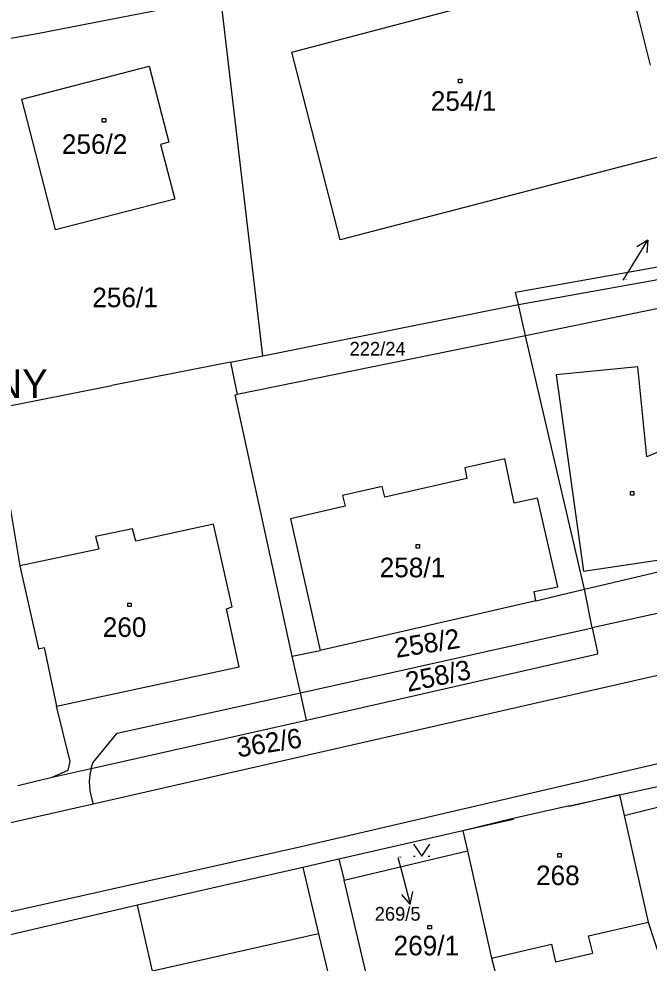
# Model space of a CAD drawing. Extents: x -468021 to -466942, y -1130484 to -1128584.
# Drawn here: x -467547 to -467492.3, y -1129179.5 to -1129097.5 of the extents above; entities that cross this region are included whole.
import ezdxf

# ---------------------------------------------------------------- set-up
doc = ezdxf.new("R2010")
doc.units = 0
doc.layers.add('23-Popisy-budov', color=7, linetype='Continuous')
doc.layers.add('DKM', color=7, linetype='Continuous')

msp = doc.modelspace()

# ---------------------------------------------------------------- linework, layer by layer
at = {"layer": 'DKM'}
for p, q in [((-467523.29, -1129100.4), (-467498.34, -1129093.8)), ((-467529.45, -1129095.67), (-467545.39, -1129098.81)), ((-467525.83, -1129126.76), (-467529.45, -1129095.67)), ((-467493.1, -1129097.8), (-467493.53, -1129096.11)), ((-467492.16, -1129101.51), (-467493.1, -1129097.8)), ((-467545.39, -1129098.81), (-467555.59, -1129100.6)), ((-467519.11, -1129116.69), (-467523.29, -1129100.4)), ((-467546.73, -1129104.46), (-467535.68, -1129101.62)), ((-467535.68, -1129101.62), (-467533.97, -1129108.2)), ((-467508.85, -1129102.74), (-467508.55, -1129102.74)), ((-467508.85, -1129103.04), (-467508.85, -1129102.74)), ((-467508.55, -1129102.74), (-467508.55, -1129103.04)), ((-467508.55, -1129103.04), (-467508.85, -1129103.04)), ((-467543.8, -1129115.81), (-467546.73, -1129104.46)), ((-467539.75, -1129106.16), (-467539.45, -1129106.16)), ((-467539.75, -1129106.46), (-467539.75, -1129106.16)), ((-467539.45, -1129106.46), (-467539.75, -1129106.46)), ((-467539.45, -1129106.16), (-467539.45, -1129106.46)), ((-467533.97, -1129108.2), (-467534.7, -1129108.4)), ((-467534.7, -1129108.4), (-467533.47, -1129113.15)), ((-467487.03, -1129108.35), (-467494.19, -1129110.21)), ((-467494.19, -1129110.21), (-467519.11, -1129116.69)), ((-467533.47, -1129113.15), (-467543.8, -1129115.81)), ((-467503.88, -1129121.24), (-467476.48, -1129116.33)), ((-467503.63, -1129122.31), (-467475.76, -1129117.27)), ((-467493.97, -1129119.26), (-467492.398, -1129116.704)), ((-467492.398, -1129116.704), (-467493.348, -1129117.294)), ((-467492.398, -1129116.704), (-467492.496, -1129117.818)), ((-467494.54, -1129120.18), (-467493.97, -1129119.26)), ((-467503.63, -1129122.31), (-467503.88, -1129121.24)), ((-467525.83, -1129126.76), (-467503.63, -1129122.31)), ((-467503.02, -1129125.01), (-467503.63, -1129122.31)), ((-467490.64, -1129122.49), (-467503.02, -1129125.01)), ((-467503.02, -1129125.01), (-467528.04, -1129130.11)), ((-467497.9, -1129147.01), (-467503.02, -1129125.01)), ((-467528.63, -1129127.32), (-467538.93, -1129129.34)), ((-467528.63, -1129127.32), (-467525.83, -1129126.76)), ((-467528.63, -1129127.32), (-467528.04, -1129130.11)), ((-467493.27, -1129127.72), (-467500.37, -1129128.4)), ((-467492.5, -1129135.53), (-467493.27, -1129127.72)), ((-467500.37, -1129128.4), (-467498, -1129145.46)), ((-467549.23, -1129131.37), (-467538.93, -1129129.34)), ((-467528.23, -1129130.15), (-467528.04, -1129130.11)), ((-467523.26, -1129152.83), (-467528.23, -1129130.15)), ((-467549.23, -1129131.37), (-467546.9, -1129145)), ((-467490.21, -1129134.54), (-467492.5, -1129135.53)), ((-467504.82, -1129135.69), (-467508.29, -1129136.5)), ((-467504.01, -1129139.55), (-467504.82, -1129135.69)), ((-467508.29, -1129136.5), (-467508.11, -1129137.4)), ((-467508.11, -1129137.4), (-467515.24, -1129139.03)), ((-467515.45, -1129138.12), (-467518.89, -1129138.9)), ((-467515.24, -1129139.03), (-467515.45, -1129138.12)), ((-467493.91, -1129138.55), (-467493.61, -1129138.55)), ((-467493.91, -1129138.85), (-467493.91, -1129138.55)), ((-467493.61, -1129138.55), (-467493.61, -1129138.85)), ((-467518.89, -1129138.9), (-467518.68, -1129139.81)), ((-467501.99, -1129139.11), (-467504.01, -1129139.55)), ((-467500.22, -1129146.81), (-467501.99, -1129139.11)), ((-467493.61, -1129138.85), (-467493.91, -1129138.85)), ((-467518.68, -1129139.81), (-467523.41, -1129140.92)), ((-467523.41, -1129140.92), (-467520.85, -1129152.34)), ((-467537.12, -1129141.79), (-467540.34, -1129142.46)), ((-467536.85, -1129142.86), (-467537.12, -1129141.79)), ((-467530.11, -1129141.38), (-467536.85, -1129142.86)), ((-467528.49, -1129148.55), (-467530.11, -1129141.38)), ((-467540.34, -1129142.46), (-467540.06, -1129143.55)), ((-467540.06, -1129143.55), (-467546.9, -1129145)), ((-467512.52, -1129143.15), (-467512.22, -1129143.15)), ((-467512.52, -1129143.45), (-467512.52, -1129143.15)), ((-467512.22, -1129143.45), (-467512.52, -1129143.45)), ((-467512.22, -1129143.15), (-467512.22, -1129143.45)), ((-467498, -1129145.46), (-467485.72, -1129143.62)), ((-467497.9, -1129147.01), (-467485.62, -1129144.14)), ((-467546.9, -1129145), (-467545.3, -1129152.19)), ((-467502.27, -1129147.23), (-467500.22, -1129146.81)), ((-467502.12, -1129148.03), (-467497.9, -1129147.01)), ((-467497.24, -1129150.38), (-467497.9, -1129147.01)), ((-467502.12, -1129148.03), (-467502.27, -1129147.23)), ((-467483.67, -1129147.4), (-467497.24, -1129150.38)), ((-467537.54, -1129148.24), (-467537.24, -1129148.24)), ((-467537.54, -1129148.54), (-467537.54, -1129148.24)), ((-467537.24, -1129148.54), (-467537.54, -1129148.54)), ((-467537.24, -1129148.24), (-467537.24, -1129148.54)), ((-467528.97, -1129148.72), (-467528.49, -1129148.55)), ((-467502.12, -1129148.03), (-467520.85, -1129152.34)), ((-467527.88, -1129153.77), (-467528.97, -1129148.72)), ((-467522.56, -1129156.02), (-467497.24, -1129150.38)), ((-467497.24, -1129150.38), (-467496.76, -1129152.52)), ((-467545.3, -1129152.19), (-467544.81, -1129152.08)), ((-467544.81, -1129152.08), (-467543.72, -1129157.18)), ((-467540.53, -1129165.65), (-467482.53, -1129152.42)), ((-467523.26, -1129152.83), (-467520.85, -1129152.34)), ((-467522.04, -1129158.39), (-467496.73, -1129152.64)), ((-467496.73, -1129152.64), (-467496.76, -1129152.52)), ((-467522.56, -1129156.02), (-467523.26, -1129152.83)), ((-467543.72, -1129157.18), (-467527.88, -1129153.77)), ((-467538.47, -1129159.54), (-467522.56, -1129156.02)), ((-467522.04, -1129158.39), (-467522.56, -1129156.02)), ((-467542.53, -1129161.98), (-467543.72, -1129157.18)), ((-467540.73, -1129162.6), (-467522.04, -1129158.39)), ((-467540.57, -1129162.09), (-467538.47, -1129159.54)), ((-467487.35, -1129161.2), (-467522.5, -1129169.4)), ((-467544.09, -1129163.36), (-467540.73, -1129162.6)), ((-467542.72, -1129162.75), (-467542.53, -1129161.98)), ((-467540.73, -1129162.6), (-467540.57, -1129162.09)), ((-467547.08, -1129164.06), (-467544.09, -1129163.36)), ((-467544.09, -1129163.36), (-467542.72, -1129162.75)), ((-467494.86, -1129164.89), (-467491.56, -1129164.15)), ((-467499.21, -1129165.83), (-467494.86, -1129164.89)), ((-467494.86, -1129164.89), (-467499.19, -1129165.9)), ((-467494.86, -1129164.89), (-467494.46, -1129166.68)), ((-467494.46, -1129166.68), (-467486.35, -1129164.66)), ((-467574.2, -1129173.33), (-467540.53, -1129165.65)), ((-467499.21, -1129165.83), (-467504.1, -1129166.95)), ((-467499.19, -1129165.9), (-467499.21, -1129165.83)), ((-467494.46, -1129166.68), (-467492.36, -1129175.94)), ((-467504.1, -1129166.95), (-467508.45, -1129168.02)), ((-467504.08, -1129167.02), (-467508.45, -1129168.02)), ((-467504.08, -1129167.02), (-467504.1, -1129166.95)), ((-467508.45, -1129168.02), (-467519.21, -1129170.47)), ((-467508.45, -1129168.02), (-467508.06, -1129169.75)), ((-467512.73, -1129169.16), (-467512.03, -1129170.21)), ((-467512.03, -1129170.21), (-467511.33, -1129169.16)), ((-467522.5, -1129169.4), (-467574.83, -1129181.1)), ((-467518.77, -1129172.3), (-467508.06, -1129169.75)), ((-467508.06, -1129169.75), (-467505.98, -1129179.07)), ((-467500.22, -1129169.99), (-467499.92, -1129169.99)), ((-467500.22, -1129170.29), (-467500.22, -1129169.99)), ((-467499.92, -1129169.99), (-467499.92, -1129170.29)), ((-467519.21, -1129170.47), (-467522.36, -1129171.19)), ((-467519.21, -1129170.47), (-467518.77, -1129172.3)), ((-467514.09, -1129170.33), (-467513.79, -1129171.47)), ((-467512.73, -1129170.21), (-467512.59, -1129170.21)), ((-467511.47, -1129170.21), (-467511.33, -1129170.21)), ((-467499.92, -1129170.29), (-467500.22, -1129170.29)), ((-467522.36, -1129171.19), (-467535.8, -1129174.25)), ((-467522.36, -1129171.19), (-467521, -1129176.94)), ((-467513.79, -1129171.47), (-467513.021, -1129174.37)), ((-467515.8, -1129184.77), (-467518.77, -1129172.3)), ((-467513.021, -1129174.37), (-467513.761, -1129173.531)), ((-467513.021, -1129174.37), (-467512.794, -1129173.275)), ((-467536.7, -1129174.46), (-467551.6, -1129177.94)), ((-467535.8, -1129174.25), (-467536.7, -1129174.46)), ((-467535.38, -1129180.2), (-467536.7, -1129174.46)), ((-467511.49, -1129176.22), (-467511.19, -1129176.22)), ((-467511.49, -1129176.52), (-467511.49, -1129176.22)), ((-467511.19, -1129176.52), (-467511.49, -1129176.52)), ((-467511.19, -1129176.22), (-467511.19, -1129176.52)), ((-467497.54, -1129177.14), (-467492.36, -1129175.94)), ((-467492.36, -1129175.94), (-467491.28, -1129179.3)), ((-467521, -1129176.94), (-467535.38, -1129180.2)), ((-467521, -1129176.94), (-467518.12, -1129188.82)), ((-467497.19, -1129178.63), (-467497.54, -1129177.14)), ((-467505.98, -1129179.07), (-467500.77, -1129177.86)), ((-467500.77, -1129177.86), (-467500.42, -1129179.38)), ((-467500.42, -1129179.38), (-467497.19, -1129178.63)), ((-467505.98, -1129179.07), (-467505.1, -1129182.29))]:
    msp.add_line(p, q, dxfattribs=at)
msp.add_arc((-467535.903, -1129163.815), 4.978, 165.8719, 201.63156, dxfattribs=at)

# ---------------------------------------------------------------- texts
at = {"layer": '23-Popisy-budov'}
msp.add_text('ŠATNY', height=2.5, dxfattribs=at).set_placement((-467555.627, -1129130.421))
at = {"layer": 'DKM'}
for s, height, p in [('254/1', 1.7, (-467511.24, -1129105.48)), ('256/2', 1.7, (-467543.26, -1129109.22)), ('256/1', 1.7, (-467540.62, -1129122.54)), ('222/21', 0.1, (-467494.54, -1129120.18)), ('222/24', 1.19, (-467518.29, -1129126.74)), ('258/1', 1.7, (-467515.679, -1129145.99)), ('260', 1.7, (-467539.716, -1129151.17)), ('269/5', 0.1, (-467514.09, -1129170.33)), ('268', 1.7, (-467502.11, -1129172.72)), ('269/5', 1.19, (-467516.11, -1129175.81)), ('269/1', 1.7, (-467514.47, -1129178.82))]:
    msp.add_text(s, height=height, dxfattribs=at).set_placement(p)
for s, rotation, p in [('258/2', 9, (-467514.233, -1129152.995)), ('258/3', 11.7, (-467513.223, -1129155.951)), ('362/6', 9, (-467527.957, -1129161.639))]:
    msp.add_text(s, height=1.7, rotation=rotation, dxfattribs=at).set_placement(p)

doc.saveas('drawing.dxf')
